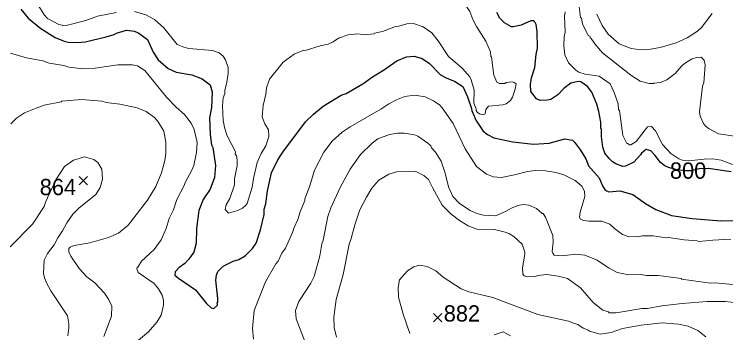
# Model space of a CAD drawing. Extents: x 265.7 to 292.1, y 7676.2 to 7704.2.
# Drawn here: x 276.42 to 279.917, y 7686.563 to 7688.129 of the extents above; entities that cross this region are included whole.
import ezdxf
from ezdxf.enums import TextEntityAlignment as Align

# ---------------------------------------------------------------- set-up
doc = ezdxf.new("R2010")
doc.units = 0
doc.header["$LTSCALE"] = 0.032
for name, color, linetype, lineweight in [('1', 7, 'Continuous', 25), ('2', 7, 'Continuous', 13), ('21', 7, 'Continuous', 25)]:
    doc.layers.add(name, color=color, linetype=linetype, lineweight=lineweight)
doc.layers.add('61', color=7, linetype='Continuous')

msp = doc.modelspace()

# ---------------------------------------------------------------- linework, layer by layer
at = {"layer": '1'}
for points in [[(276.4522, 7688.1537), (276.4889, 7688.109), (276.5512, 7688.0587), (276.6222, 7688.0148), (276.6661, 7687.9965), (276.6861, 7687.9917), (276.7299, 7687.9893), (276.7682, 7687.9925), (276.872, 7688.0172), (276.9119, 7688.03), (276.923, 7688.0364), (276.9725, 7688.0499), (277.0108, 7688.046), (277.0332, 7688.0356), (277.0755, 7688.0045), (277.1026, 7687.943), (277.1273, 7687.9055), (277.1776, 7687.8624), (277.2167, 7687.8449), (277.2933, 7687.8305), (277.3444, 7687.8121), (277.3827, 7687.7818), (277.3922, 7687.7467), (277.3891, 7687.6701), (277.3803, 7687.6191), (277.3827, 7687.5377), (277.3898, 7687.4866), (277.397, 7687.473), (277.4098, 7687.3845), (277.405, 7687.327), (277.3827, 7687.2695), (277.3492, 7687.2177), (277.3268, 7687.1642), (277.3156, 7687.0748), (277.3148, 7687.0038), (277.3029, 7686.9599), (277.2773, 7686.9232), (277.259, 7686.9041), (277.2303, 7686.8833), (277.2111, 7686.8626), (277.2103, 7686.8466), (277.2279, 7686.8307), (277.3109, 7686.774), (277.3651, 7686.707), (277.3883, 7686.6862), (277.4018, 7686.683), (277.4194, 7686.699), (277.4178, 7686.7118), (277.4202, 7686.7126), (277.421, 7686.7317), (277.4114, 7686.8211), (277.4146, 7686.8466), (277.421, 7686.8642), (277.4465, 7686.8905), (277.496, 7686.9144), (277.5247, 7686.9224), (277.5558, 7686.9416), (277.5909, 7686.9775), (277.6085, 7687.0038), (277.6308, 7687.0685), (277.6492, 7687.1451), (277.6492, 7687.1706), (277.6572, 7687.1961), (277.6651, 7687.26), (277.6851, 7687.3493), (277.7154, 7687.4132), (277.7402, 7687.4515), (277.8511, 7687.5999), (277.8902, 7687.6382), (277.9381, 7687.6773), (278.0266, 7687.7308), (278.0514, 7687.7395), (278.1328, 7687.7866), (278.1806, 7687.8217), (278.2349, 7687.8544), (278.3011, 7687.8999), (278.3482, 7687.9191), (278.3865, 7687.9231), (278.4248, 7687.9111)], [(279.1909, 7687.7978), (279.1558, 7687.7898), (279.1206, 7687.7643), (279.0919, 7687.7332), (279.0568, 7687.71), (279.0392, 7687.706), (279.0041, 7687.7052), (278.9874, 7687.7124), (278.9594, 7687.7483), (278.9578, 7687.7834), (278.9626, 7687.817), (278.9786, 7687.8664), (278.985, 7687.9303), (278.9914, 7687.9622), (278.9898, 7688.0436), (278.985, 7688.0787), (278.9802, 7688.089), (278.9738, 7688.0946), (278.9746, 7688.097), (278.9595, 7688.0962), (278.9116, 7688.0755), (278.8725, 7688.0667), (278.8637, 7688.0675), (278.8294, 7688.0874), (278.807, 7688.109), (278.7919, 7688.1369)], [(278.4248, 7687.9111), (278.4607, 7687.8872), (278.515, 7687.8313), (278.5461, 7687.8145), (278.5844, 7687.8002), (278.6243, 7687.7731), (278.6474, 7687.7228)], [(279.3034, 7687.5983), (279.2938, 7687.651), (279.2834, 7687.6861), (279.2587, 7687.7459), (279.2371, 7687.7731), (279.2052, 7687.797), (279.1909, 7687.7978)], [(278.6474, 7687.7228), (278.6682, 7687.6661), (278.669, 7687.6518), (278.6746, 7687.6446), (278.6881, 7687.6079), (278.7256, 7687.5536), (278.7464, 7687.5377), (278.7775, 7687.5209), (278.8701, 7687.5009), (278.9722, 7687.4898), (279.0488, 7687.4954), (279.1254, 7687.5161), (279.1637, 7687.5097), (279.1741, 7687.5002), (279.2036, 7687.4603), (279.2292, 7687.418), (279.2419, 7687.3837), (279.2954, 7687.3246), (279.3113, 7687.2855), (279.3241, 7687.264), (279.3425, 7687.256), (279.3967, 7687.26), (279.4606, 7687.2432), (279.522, 7687.1993), (279.5739, 7687.169), (279.6505, 7687.1403), (279.7526, 7687.1243), (279.8931, 7687.1131), (279.9569, 7687.1147)], [(279.9433, 7687.3549), (279.83, 7687.3701), (279.7848, 7687.3682), (279.7471, 7687.3587), (279.7188, 7687.3587), (279.6774, 7687.3644), (279.6359, 7687.3757), (279.617, 7687.3844), (279.5962, 7687.4004), (279.5707, 7687.4339), (279.5483, 7687.4571), (279.5252, 7687.4642), (279.5029, 7687.4467), (279.4981, 7687.4371), (279.4645, 7687.4012), (279.4239, 7687.382), (279.4111, 7687.3812), (279.376, 7687.3932), (279.36, 7687.4028), (279.3433, 7687.4196), (279.3233, 7687.4467), (279.3129, 7687.4754), (279.3058, 7687.5281), (279.3058, 7687.5632), (279.3026, 7687.568), (279.3034, 7687.5983)]]:
    msp.add_lwpolyline(points, dxfattribs=at)
at = {"layer": '2'}
for points in [[(278.5238, 7688.283), (278.5629, 7688.2455), (278.6036, 7688.2135), (278.6427, 7688.1673), (278.6586, 7688.1425), (278.6738, 7688.1026), (278.6913, 7688.0691)], [(279.19, 7688.2191), (279.2036, 7688.1122), (279.2076, 7688.1098), (279.2132, 7688.0819), (279.2411, 7688.0244), (279.2499, 7688.0188), (279.2507, 7688.0132), (279.2563, 7688.0093), (279.2738, 7687.9829), (279.3105, 7687.939), (279.451, 7687.8297), (279.4957, 7687.8002), (279.5404, 7687.789), (279.5619, 7687.7882), (279.5627, 7687.7906), (279.5962, 7687.7938), (279.6281, 7687.8066), (279.6688, 7687.8369), (279.7016, 7687.8752), (279.7191, 7687.8896), (279.7526, 7687.9095), (279.775, 7687.9167), (279.7957, 7687.9183), (279.8109, 7687.9023), (279.8153, 7687.8795), (279.8085, 7687.7922), (279.8021, 7687.7755), (279.7877, 7687.6486), (279.7909, 7687.6286), (279.8069, 7687.5919), (279.8172, 7687.5792), (279.8356, 7687.5656), (279.8819, 7687.5416), (279.9713, 7687.5273)], [(276.9231, 7688.1369), (276.8289, 7688.1202), (276.7714, 7688.0986), (276.6757, 7688.0739), (276.6581, 7688.0723), (276.6565, 7688.0755), (276.639, 7688.0779), (276.5831, 7688.1082), (276.5688, 7688.1242), (276.5384, 7688.1728)], [(277.0667, 7688.1266), (277.0108, 7688.1417)], [(277.3939, 7687.951), (277.2789, 7687.9598), (277.2534, 7687.9662), (277.2215, 7687.9797), (277.1561, 7688.0627), (277.1098, 7688.1034), (277.0667, 7688.1266)], [(279.127, 7688.1409), (279.1238, 7688.1186), (279.1278, 7688.0404), (279.123, 7688.018), (279.1206, 7687.9734), (279.1262, 7687.9287), (279.1438, 7687.8904), (279.1805, 7687.8537), (279.1941, 7687.8449), (279.226, 7687.8337), (279.2954, 7687.8241), (279.3481, 7687.7874), (279.3688, 7687.7435), (279.3888, 7687.6877), (279.3895, 7687.6613), (279.3951, 7687.655), (279.4119, 7687.5329), (279.4302, 7687.4938), (279.435, 7687.4938), (279.4438, 7687.4866), (279.451, 7687.4866), (279.4773, 7687.5026), (279.5324, 7687.576), (279.5515, 7687.5768), (279.5715, 7687.5552), (279.6058, 7687.4882), (279.6473, 7687.4435), (279.6856, 7687.418), (279.7047, 7687.4108), (279.7335, 7687.4076), (279.8101, 7687.4172), (279.8516, 7687.4188), (279.8947, 7687.4116), (279.9505, 7687.3908)], [(279.2834, 7688.1298), (279.309, 7688.0739), (279.3385, 7688.0316), (279.3927, 7687.9837), (279.4526, 7687.9606), (279.5005, 7687.9542), (279.5468, 7687.9574), (279.5946, 7687.9654), (279.6728, 7687.9885), (279.7271, 7688.0132), (279.7782, 7688.0452), (279.7973, 7688.0635), (279.85, 7688.1329)], [(278.6913, 7688.0691), (278.7376, 7687.9973), (278.7608, 7687.9446), (278.7631, 7687.9207), (278.7663, 7687.9183), (278.7775, 7687.8297), (278.7927, 7687.7954), (278.8046, 7687.789), (278.8318, 7687.789), (278.8382, 7687.793), (278.8669, 7687.7962), (278.8765, 7687.7938), (278.8868, 7687.7866), (278.8828, 7687.7611), (278.8685, 7687.7212), (278.8597, 7687.7052), (278.8382, 7687.6885), (278.8222, 7687.6829), (278.7504, 7687.6765), (278.7384, 7687.6606), (278.7344, 7687.639), (278.7249, 7687.635), (278.7065, 7687.639), (278.6945, 7687.647), (278.6897, 7687.655), (278.6897, 7687.6645), (278.6794, 7687.6925), (278.6802, 7687.7563), (278.6658, 7687.8058), (278.6586, 7687.8209), (278.6203, 7687.8648), (278.5541, 7687.9215), (278.5038, 7687.9989), (278.4719, 7688.038), (278.4296, 7688.0667), (278.3817, 7688.0827), (278.3498, 7688.0819), (278.3099, 7688.0699), (278.294, 7688.0683), (278.2301, 7688.0444), (278.191, 7688.0364), (278.1894, 7688.0332), (278.1423, 7688.0276), (278.1088, 7688.0324), (278.0609, 7688.0284), (278.0131, 7688.0108), (277.9875, 7687.9933), (277.9636, 7687.9821), (277.9237, 7687.9741), (277.8503, 7687.951), (277.8439, 7687.9518), (277.796, 7687.9318), (277.7426, 7687.8935), (277.6747, 7687.809), (277.6596, 7687.7675), (277.6564, 7687.7356), (277.6444, 7687.6797), (277.6388, 7687.6238), (277.6524, 7687.5903), (277.6691, 7687.56), (277.6723, 7687.5281), (277.6564, 7687.4818), (277.634, 7687.4443), (277.6149, 7687.4004), (277.5957, 7687.3206), (277.5901, 7687.2791), (277.5646, 7687.1993), (277.5574, 7687.1889), (277.5423, 7687.1762), (277.5199, 7687.1642), (277.4736, 7687.1514), (277.4577, 7687.169), (277.4625, 7687.1921), (277.4792, 7687.2233), (277.5024, 7687.2903), (277.5032, 7687.319), (277.5151, 7687.3861), (277.5159, 7687.4116), (277.5119, 7687.4347), (277.5064, 7687.4411), (277.5072, 7687.4523), (277.4657, 7687.5345), (277.4529, 7687.5744), (277.4465, 7687.6063), (277.4433, 7687.6781), (277.4473, 7687.718), (277.4545, 7687.7388), (277.4545, 7687.7547), (277.4649, 7687.7946), (277.4712, 7687.8377), (277.4712, 7687.8664), (277.4593, 7687.9047), (277.4465, 7687.9231), (277.4282, 7687.939), (277.3939, 7687.951)], [(277.0116, 7686.5099), (277.0795, 7686.5681), (277.1209, 7686.6152), (277.1417, 7686.6503), (277.1545, 7686.6982), (277.1537, 7686.7237), (277.1473, 7686.7477), (277.1297, 7686.7796), (277.1074, 7686.8051), (277.0292, 7686.8594), (277.0236, 7686.877), (277.0252, 7686.8849), (277.0284, 7686.8857), (277.0459, 7686.9153), (277.1082, 7686.9719), (277.1417, 7687.0206), (277.1664, 7687.0764), (277.1816, 7687.1251), (277.2023, 7687.1674), (277.2199, 7687.2185), (277.2566, 7687.2903), (277.2582, 7687.2983), (277.2933, 7687.3621), (277.3029, 7687.3861), (277.3164, 7687.4499), (277.3188, 7687.4978), (277.3053, 7687.5616), (277.2893, 7687.5935), (277.2574, 7687.6366), (277.2167, 7687.6725), (277.1688, 7687.722), (277.0619, 7687.8529), (277.0268, 7687.8752), (277.0013, 7687.88), (276.9294, 7687.88), (276.8177, 7687.864), (276.7603, 7687.8608), (276.6885, 7687.868), (276.6645, 7687.8768), (276.5927, 7687.888), (276.5608, 7687.8991), (276.481, 7687.9151), (276.4012, 7687.9374)], [(276.86, 7686.545), (276.8991, 7686.6439), (276.8999, 7686.6934), (276.8839, 7686.7285), (276.864, 7686.7573), (276.8161, 7686.8083), (276.7778, 7686.8378), (276.7387, 7686.8793), (276.698, 7686.9392), (276.6884, 7686.9615), (276.6884, 7686.9775), (276.6956, 7686.9839), (276.7156, 7686.9927), (276.7922, 7687.0046), (276.8832, 7687.031), (276.9326, 7687.0533), (276.9797, 7687.0924), (277.0747, 7687.2153), (277.1154, 7687.2823), (277.1441, 7687.3493), (277.1608, 7687.41), (277.1648, 7687.4435), (277.1648, 7687.4994), (277.1553, 7687.5536), (277.1281, 7687.5999), (277.1098, 7687.6206), (277.0683, 7687.6502), (277.0252, 7687.6693), (276.939, 7687.6869), (276.872, 7687.6949), (276.8512, 7687.7012), (276.7507, 7687.71), (276.6541, 7687.7012), (276.6502, 7687.698), (276.5679, 7687.6813), (276.5273, 7687.6677), (276.4714, 7687.6438), (276.4315, 7687.6175), (276.4044, 7687.5903)], [(279.9425, 7687.023), (279.8532, 7687.019), (279.7853, 7687.0118), (279.7766, 7687.015), (279.7127, 7687.0198), (279.6361, 7687.031), (279.6234, 7687.0294), (279.5595, 7687.0389), (279.5084, 7687.0389), (279.4829, 7687.0349), (279.4318, 7687.0381), (279.4095, 7687.0469), (279.3696, 7687.0748), (279.3473, 7687.0964), (279.3074, 7687.1123), (279.2435, 7687.1123), (279.218, 7687.1155), (279.202, 7687.1235), (279.198, 7687.1307), (279.2012, 7687.1562), (279.2252, 7687.2328), (279.222, 7687.2584), (279.2092, 7687.2839), (279.1773, 7687.3118), (279.1206, 7687.339), (279.0823, 7687.3501), (279.0313, 7687.3597), (278.9802, 7687.3613), (278.9419, 7687.3565), (278.8781, 7687.339), (278.8142, 7687.327), (278.7759, 7687.3302), (278.7408, 7687.3422), (278.6913, 7687.3805), (278.6371, 7687.4674), (278.5772, 7687.5919), (278.5238, 7687.6685), (278.5118, 7687.6813), (278.4807, 7687.7036), (278.4392, 7687.7236), (278.3881, 7687.7308), (278.3394, 7687.7244), (278.2987, 7687.7084), (278.2604, 7687.6885), (278.2221, 7687.6621), (278.0705, 7687.576), (278.0322, 7687.5496), (277.9827, 7687.5049), (277.9412, 7687.4515), (277.8958, 7687.3621), (277.8726, 7687.2855), (277.8479, 7687.2217), (277.8487, 7687.2129), (277.8247, 7687.1578), (277.8136, 7687.1195), (277.796, 7687.0812), (277.788, 7687.0557), (277.7529, 7686.9791), (277.7354, 7686.9536), (277.717, 7686.9153), (277.7066, 7686.9025), (277.6556, 7686.8131), (277.5989, 7686.6727), (277.5917, 7686.5833), (277.5965, 7686.5322)], [(279.9537, 7686.8011), (279.8643, 7686.8091), (279.842, 7686.8075), (279.7, 7686.8267), (279.7, 7686.8299), (279.5851, 7686.8442), (279.5276, 7686.8442), (279.4989, 7686.8498), (279.4414, 7686.8474), (279.384, 7686.8594), (279.3409, 7686.8817), (279.2842, 7686.9192), (279.2244, 7686.9448), (279.1797, 7686.9488), (279.1127, 7686.9408), (279.0744, 7686.944), (279.0664, 7686.9536), (279.064, 7686.9631), (279.0696, 7687.0078), (279.0664, 7687.0413), (279.0313, 7687.1307), (279.0193, 7687.1499), (279.0153, 7687.1499), (278.9874, 7687.1746), (278.9499, 7687.1905), (278.9211, 7687.1929), (278.8956, 7687.1889), (278.8637, 7687.1762), (278.835, 7687.1586), (278.7855, 7687.1379), (278.7264, 7687.1411), (278.6929, 7687.1491), (278.661, 7687.1634), (278.6083, 7687.1977), (278.5756, 7687.2328), (278.5541, 7687.2807), (278.5381, 7687.3477), (278.5182, 7687.4068), (278.491, 7687.4515), (278.4711, 7687.4722), (278.4671, 7687.4818), (278.4527, 7687.4954), (278.4033, 7687.5289), (278.3881, 7687.5353), (278.3386, 7687.5448), (278.3035, 7687.544), (278.2652, 7687.5369), (278.2078, 7687.5161), (278.179, 7687.4954), (278.1224, 7687.4395), (278.0713, 7687.3669), (278.0218, 7687.2775), (277.9756, 7687.177), (277.962, 7687.1339), (277.9389, 7687.019), (277.9325, 7686.9998), (277.9229, 7686.9408), (277.895, 7686.8402), (277.8774, 7686.8067), (277.8192, 7686.7174), (277.8032, 7686.6727), (277.8056, 7686.6312), (277.8495, 7686.5163)], [(276.6829, 7686.5482), (276.6892, 7686.5881), (276.6892, 7686.6072), (276.6813, 7686.6455), (276.6007, 7686.7684), (276.5783, 7686.8083), (276.5688, 7686.8323), (276.5648, 7686.8562), (276.568, 7686.92), (276.5831, 7686.952), (276.6158, 7686.9958), (276.6342, 7687.0302), (276.6581, 7687.0637), (276.6789, 7687.1036), (276.7084, 7687.1467), (276.7379, 7687.1762), (276.8209, 7687.2432), (276.8433, 7687.2775), (276.8544, 7687.3174), (276.8512, 7687.3669), (276.8305, 7687.3996), (276.8113, 7687.414), (276.7651, 7687.4275), (276.7108, 7687.4116), (276.6677, 7687.3797), (276.6242, 7687.3149), (276.5737, 7687.2057), (276.5672, 7687.1834), (276.5105, 7687.0972), (276.3996, 7686.9855)], [(279.9713, 7686.7102), (279.9154, 7686.7174), (279.826, 7686.7166), (279.7032, 7686.707), (279.6026, 7686.695), (279.5324, 7686.683), (279.5037, 7686.6822), (279.3792, 7686.6607), (279.3433, 7686.6615), (279.3401, 7686.6655), (279.3129, 7686.6743), (279.2659, 7686.7118), (279.2028, 7686.7836), (279.1398, 7686.8291), (279.0935, 7686.841), (279.0377, 7686.849), (278.993, 7686.8442), (278.9818, 7686.8394), (278.9403, 7686.8378), (278.9259, 7686.8426), (278.9195, 7686.8506), (278.9187, 7686.8817), (278.9299, 7686.9488), (278.9291, 7686.9599), (278.9164, 7686.999), (278.8749, 7687.0357), (278.8541, 7687.0493), (278.8326, 7687.0581), (278.7807, 7687.0701), (278.6937, 7687.0717), (278.6514, 7687.0884), (278.6083, 7687.1147), (278.5669, 7687.1467), (278.523, 7687.1897), (278.4751, 7687.2775), (278.4567, 7687.3158), (278.4336, 7687.3358), (278.3945, 7687.3565), (278.2987, 7687.3549), (278.2604, 7687.3422), (278.2126, 7687.3134), (278.1782, 7687.2743), (278.1511, 7687.2297), (278.1184, 7687.1666), (278.0937, 7687.094), (278.0769, 7687.027), (278.0665, 7686.9982), (278.0362, 7686.8498), (278.0019, 7686.7269), (277.9907, 7686.6392), (277.9931, 7686.5897), (278.0043, 7686.5418)], [(279.8189, 7686.5434), (279.7798, 7686.5737), (279.7319, 7686.5953), (279.684, 7686.6056), (279.6042, 7686.612), (279.5005, 7686.6008), (279.4087, 7686.5833), (279.3536, 7686.5649), (279.2994, 7686.5554), (279.2475, 7686.5705), (279.2379, 7686.5777), (279.2156, 7686.5857), (279.1901, 7686.6032), (279.1637, 7686.6112), (279.1446, 7686.6208), (278.993, 7686.6527), (278.7727, 7686.7357), (278.6546, 7686.7636), (278.6163, 7686.7788), (278.5285, 7686.8363), (278.4918, 7686.8682), (278.4488, 7686.8889), (278.4112, 7686.8961), (278.3833, 7686.8873), (278.3522, 7686.8674), (278.3131, 7686.8235), (278.3067, 7686.786), (278.3083, 7686.7381), (278.3314, 7686.6551), (278.365, 7686.5594)], [(278.7791, 7686.553), (278.8238, 7686.5673), (278.8589, 7686.5482)]]:
    msp.add_lwpolyline(points, dxfattribs=at)
at = {"layer": '21'}
for p, q in [((276.7389, 7687.3315), (276.7801, 7687.2903)), ((276.7801, 7687.3315), (276.7389, 7687.2903)), ((278.481, 7686.6577), (278.5222, 7686.6165)), ((278.5222, 7686.6577), (278.481, 7686.6165))]:
    msp.add_line(p, q, dxfattribs=at)

# ---------------------------------------------------------------- texts
at = {"layer": '61'}
for s, p in [('800', (279.7319, 7687.3203)), ('864', (276.635, 7687.2395)), ('882', (278.6203, 7686.6182))]:
    msp.add_text(s, height=0.08, dxfattribs=at).set_placement(p, align=Align.CENTER)

doc.saveas('drawing.dxf')
